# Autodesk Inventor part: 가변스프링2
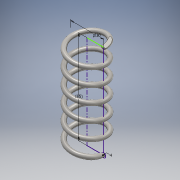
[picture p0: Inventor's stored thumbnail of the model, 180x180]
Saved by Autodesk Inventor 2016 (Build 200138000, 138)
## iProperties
Created: 2017-03
Part Number: 가변스프링2
Material: 강철, 탄소
Document SubType Name: Modeling
Designer: USER
Mass: 54.2592 g
Surface Area: 70.6401 cm^2
Volume: 6.912 cm^3
Density: 7.85 g/cm^3
Appearance: 반연마
Author: USER
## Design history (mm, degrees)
sketch "스케치1"
  geometry: L1 (0, 0)-(-15, 0); L2 (-15, 0)-(-15, 31.632); L3 (-15, 31.632)-(0, 31.632); L4 (0, 31.632)-(0, 0); C1 r 2 at (-15, 0)
  constraints: 8 end point, 2 parallel, 1 centre point, 1 coincident, 1 horizontal, 1 perpendicular
  dimensions: "d0" = 4 diameter of C1; "d1" = 30 diameter of L2 L4; "d2" = 31.63241 distance between parallel lines of L1 L3 (derived)
feature "코일1" pitch "d3" = 10; turns "d5" = 6; dims "d4" = 31.63241 (= d2), "d6" = 0, angle "d7" = 90 deg, angle "d8" = 90 deg, "d9" = 0, "d10" = 0
sketch "스케치2"
  geometry: L1 (13, 0)-(17, 0) reference; 1 further point
  constraints: 1 horizontal alignment
extrude "돌출1" cut sketch "스케치2" stored distance "d11" = 10; taper "d12" = 0 deg
node "작업 평면1"
sketch "스케치3"
  geometry: L1 (-13, 0)-(-17, 0) reference; 1 further point
  constraints: 1 horizontal alignment
extrude "돌출2" cut sketch "스케치3" stored distance "d13" = 10; taper "d14" = 0 deg
node "솔리드1"
node "절단 모서리 투영1"
node "절단 모서리 투영2"
